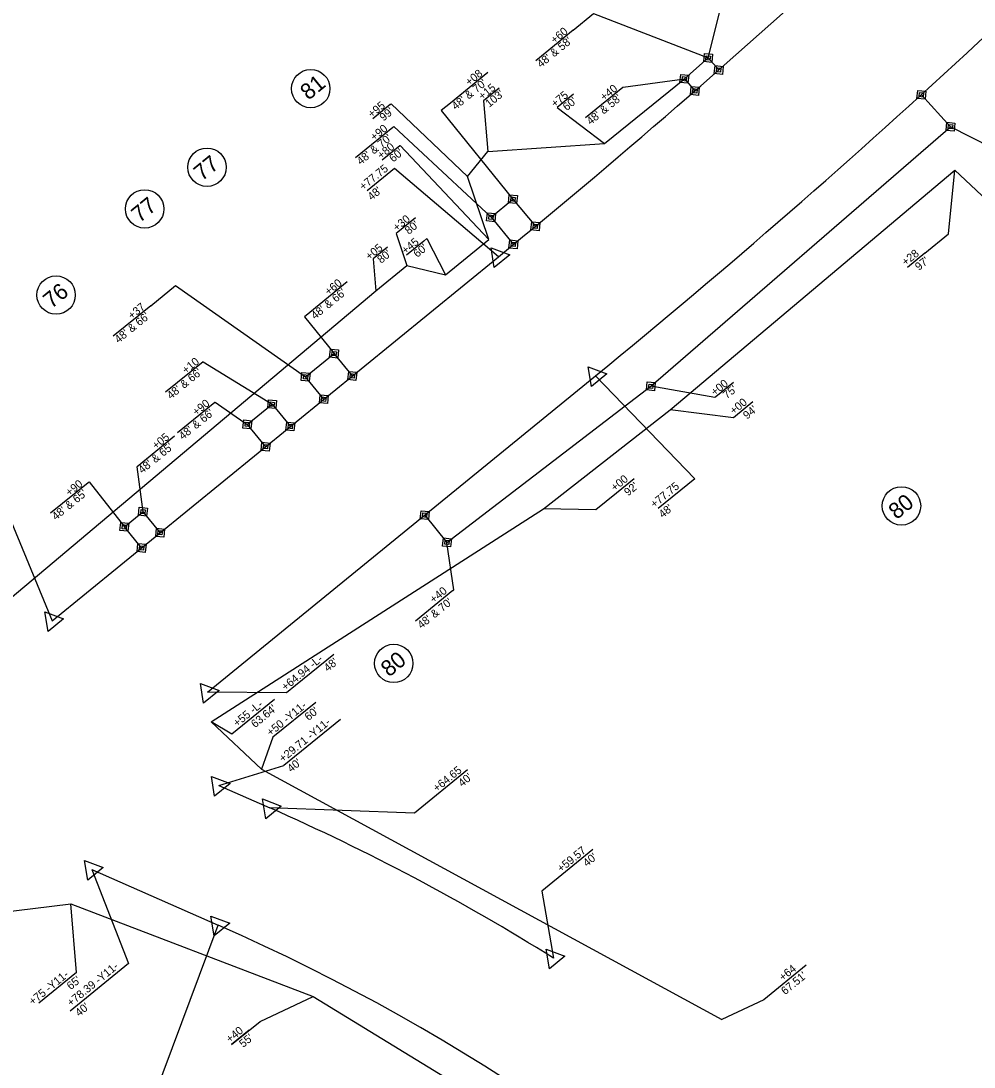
# Model space of a CAD drawing. Extents: x 2320946 to 2332748, y 597838 to 612698.
# Drawn here: x 2326517 to 2327112, y 601762 to 602416 of the extents above; entities that cross this region are included whole.
import ezdxf

# ---------------------------------------------------------------- set-up
doc = ezdxf.new("R2010")
doc.units = 0
for name, color, linetype in [('Prop Easement Construction', 7, 'Continuous'), ('Prop Easement Construction Station Offsets', 7, 'Continuous'), ('Prop Easement Permanent Drainage', 7, 'Continuous'), ('Prop Easement Permanent Drainage Station Offsets', 7, 'Continuous'), ('Prop Parcel Number CELL', 7, 'Continuous'), ('Prop ROW Marker CELL', 7, 'Continuous'), ('Prop ROW Permanent Easement CELL', 7, 'Continuous'), ('Prop ROW RW Lines', 7, 'Continuous'), ('Prop ROW Station Offsets', 7, 'Continuous')]:
    doc.layers.add(name, color=color, linetype=linetype)

msp = doc.modelspace()

# ---------------------------------------------------------------- linework, layer by layer
at = {"layer": 'Prop Easement Construction'}
for p, q in [((2326946.26, 602392.43), (2326953.47, 602421.5)), ((2326881.42, 602339.01), (2326931.39, 602379.41)), ((2326808.58, 602334.01), (2326881.42, 602339.01)), ((2326796.02, 602318.45), (2326808.58, 602334.01)), ((2326809.33, 602278.94), (2326796.02, 602318.45)), ((2326922.53, 602172.61), (2327100.38, 602322.22)), ((2327100.38, 602322.22), (2327166.14, 602260.35)), ((2326782.23, 602256.82), (2326809.33, 602278.94)), ((2326738.6, 602247.02), (2326757.97, 602262.83)), ((2326757.97, 602262.83), (2326782.23, 602256.82)), ((2326483.68, 602032.45), (2326738.6, 602247.02)), ((2326843.5, 602110.62), (2326922.53, 602172.61)), ((2326635.78, 601977.65), (2326843.5, 602110.62)), ((2326635.78, 601977.65), (2326667.14, 601948.01)), ((2326667.14, 601948.01), (2326954.86, 601791.51)), ((2326495.23, 601857.27), (2326548.1, 601863.86)), ((2326548.1, 601863.86), (2326699.47, 601805.89))]:
    msp.add_line(p, q, dxfattribs=at)
msp.add_lwpolyline([(2326699.47, 601805.89), (2326871.18, 601700.94), (2326954.31, 601627.16)], dxfattribs=at)
at = {"layer": 'Prop Easement Construction Station Offsets'}
for p, q in [((2326815.75, 602373.66), (2326805.83, 602365.56)), ((2326862.07, 602369.8), (2326851.86, 602361.46)), ((2326747.59, 602363.27), (2326736.75, 602354.41)), ((2326851.86, 602361.46), (2326881.42, 602339.01)), ((2326753.62, 602337.59), (2326742.65, 602328.63)), ((2326763.37, 602292.46), (2326752.4, 602283.5)), ((2326745.88, 602274.17), (2326736.95, 602266.89)), ((2326768.67, 602278.03), (2326757.82, 602269.18)), ((2326736.95, 602266.89), (2326738.6, 602247.02)), ((2327081.66, 602270.42), (2327070.76, 602261.52)), ((2326974.28, 602177.47), (2326963.31, 602168.51)), ((2326899.95, 602129.51), (2326888.98, 602120.56)), ((2326675.34, 601991.56), (2326648.66, 601969.79)), ((2326701.15, 601989.77), (2326674.38, 601967.91)), ((2326674.38, 601967.91), (2326667.14, 601948.01)), ((2327007.54, 601825.55), (2326980.97, 601803.86)), ((2326551.74, 601820.95), (2326528.19, 601801.73)), ((2326659.48, 601784.86), (2326648.51, 601775.91))]:
    msp.add_line(p, q, dxfattribs=at)
for points in [[(2326805.83, 602365.56), (2326808.58, 602334.01)], [(2326747.59, 602363.27), (2326748.27, 602363.82), (2326796.02, 602318.45)], [(2326753.62, 602337.59), (2326753.85, 602337.78), (2326809.33, 602278.94)], [(2327081.66, 602270.42), (2327096.43, 602282.48), (2327100.38, 602322.22)], [(2326752.4, 602283.5), (2326751.36, 602282.66), (2326757.97, 602262.83)], [(2326768.67, 602278.03), (2326770.56, 602279.57), (2326782.23, 602256.82)], [(2326963.31, 602168.51), (2326962.06, 602167.49), (2326922.53, 602172.61)], [(2326888.98, 602120.56), (2326876.03, 602109.98), (2326843.5, 602110.62)], [(2326648.66, 601969.79), (2326635.78, 601977.65)], [(2326551.74, 601820.95), (2326548.1, 601863.86)], [(2326648.51, 601775.91), (2326666.32, 601790.44), (2326699.47, 601805.89)], [(2326980.97, 601803.86), (2326954.86, 601791.51)]]:
    msp.add_lwpolyline(points, dxfattribs=at)
at = {"layer": 'Prop Easement Permanent Drainage'}
for p, q in [((2326931.39, 602379.41), (2326946.26, 602392.43)), ((2326946.26, 602392.43), (2326952.86, 602384.92)), ((2326931.39, 602379.41), (2326937.97, 602371.87)), ((2327097.65, 602349.45), (2327079.47, 602369.41)), ((2326910.44, 602187.28), (2327097.65, 602349.45)), ((2326810.63, 602292.93), (2326824.32, 602304.21)), ((2326824.32, 602304.21), (2326838.34, 602287.25)), ((2326810.63, 602292.93), (2326824.58, 602275.92)), ((2326694.78, 602193.17), (2326712.6, 602207.71)), ((2326723.98, 602193.77), (2326712.6, 602207.71)), ((2326706.16, 602179.22), (2326694.78, 602193.17)), ((2326783.11, 602089.71), (2326910.44, 602187.28)), ((2326658.37, 602163.44), (2326673.86, 602176.09)), ((2326673.86, 602176.09), (2326685.25, 602162.15)), ((2326658.37, 602163.44), (2326669.76, 602149.5)), ((2326581.54, 602099.43), (2326593.16, 602108.91)), ((2326593.16, 602108.91), (2326603.91, 602095.75)), ((2326769.2, 602106.76), (2326783.11, 602089.71)), ((2326592.29, 602086.26), (2326581.54, 602099.43))]:
    msp.add_line(p, q, dxfattribs=at)
at = {"layer": 'Prop Easement Permanent Drainage Station Offsets'}
for p, q in [((2326861.9, 602409.71), (2326838.55, 602390.64)), ((2326808.63, 602383.36), (2326785.28, 602364.29)), ((2326892.9, 602373.99), (2326869.55, 602354.93)), ((2326749.29, 602348.99), (2326725.94, 602329.93)), ((2327123.4, 602336.27), (2327097.65, 602349.45)), ((2326720.76, 602252.47), (2326697.41, 602233.4)), ((2326598.02, 602237.6), (2326574.66, 602218.53)), ((2326630.69, 602202.59), (2326607.34, 602183.53)), ((2326962.05, 602189.69), (2326951.08, 602180.74)), ((2326638.16, 602177.23), (2326614.81, 602158.16)), ((2326612.8, 602156.06), (2326589.45, 602137)), ((2326558.86, 602126.97), (2326535.5, 602107.9)), ((2326786.81, 602059.59), (2326763.46, 602040.52))]:
    msp.add_line(p, q, dxfattribs=at)
for points in [[(2326861.9, 602409.71), (2326874.72, 602420.17), (2326946.26, 602392.43)], [(2326892.9, 602373.99), (2326893.22, 602374.25), (2326931.39, 602379.41)], [(2326785.28, 602364.29), (2326779.51, 602359.59), (2326824.32, 602304.21)], [(2326749.29, 602348.99), (2326749.96, 602349.54), (2326810.63, 602292.93)], [(2326598.02, 602237.6), (2326613.53, 602250.26), (2326694.78, 602193.17)], [(2326697.41, 602233.4), (2326694.06, 602230.67), (2326712.6, 602207.71)], [(2326630.69, 602202.59), (2326630.73, 602202.62), (2326673.86, 602176.09)], [(2326951.08, 602180.74), (2326950.47, 602180.24), (2326910.44, 602187.28)], [(2326638.16, 602177.23), (2326638.29, 602177.33), (2326658.37, 602163.44)], [(2326589.45, 602137), (2326589.32, 602136.89), (2326593.16, 602108.91)], [(2326558.86, 602126.97), (2326559.65, 602127.62), (2326581.54, 602099.43)], [(2326786.81, 602059.59), (2326787.45, 602060.11), (2326783.11, 602089.71)]]:
    msp.add_lwpolyline(points, dxfattribs=at)
at = {"layer": 'Prop Parcel Number CELL'}
for p, q in [((2326697.99, 602373.29), (2326697.99, 602373.29)), ((2326633.19, 602324.17), (2326633.19, 602324.17)), ((2326594.23, 602298.12), (2326594.23, 602298.12)), ((2326538.92, 602244.29), (2326538.92, 602244.29)), ((2327067.03, 602112.52), (2327067.03, 602112.52)), ((2326749.87, 602014.1), (2326749.87, 602014.1))]:
    msp.add_line(p, q, dxfattribs=at)
for centre in [(2326697.99, 602373.29), (2326633.19, 602324.17), (2326594.23, 602298.12), (2326538.92, 602244.29), (2327067.03, 602112.52), (2326749.87, 602014.1)]:
    msp.add_circle(centre, 12, dxfattribs=at)
at = {"layer": 'Prop ROW Marker CELL'}
for p, q in [((2326946.26, 602392.43), (2326946.26, 602392.43)), ((2326952.86, 602384.92), (2326952.86, 602384.92)), ((2326931.39, 602379.41), (2326931.39, 602379.41)), ((2326937.97, 602371.87), (2326937.97, 602371.87)), ((2327079.47, 602369.41), (2327079.47, 602369.41)), ((2327097.65, 602349.45), (2327097.65, 602349.45)), ((2326824.32, 602304.21), (2326824.32, 602304.21)), ((2326810.63, 602292.93), (2326810.63, 602292.93)), ((2326838.34, 602287.25), (2326838.34, 602287.25)), ((2326824.58, 602275.92), (2326824.58, 602275.92)), ((2326815.2, 602268.24), (2326815.2, 602268.24)), ((2326712.6, 602207.71), (2326712.6, 602207.71)), ((2326694.78, 602193.17), (2326694.78, 602193.17)), ((2326723.98, 602193.77), (2326723.98, 602193.77)), ((2326875.91, 602193.87), (2326875.91, 602193.87)), ((2326910.44, 602187.28), (2326910.44, 602187.28)), ((2326673.86, 602176.09), (2326673.86, 602176.09)), ((2326706.16, 602179.22), (2326706.16, 602179.22)), ((2326658.37, 602163.44), (2326658.37, 602163.44)), ((2326685.25, 602162.15), (2326685.25, 602162.15)), ((2326669.76, 602149.5), (2326669.76, 602149.5)), ((2326593.16, 602108.91), (2326593.16, 602108.91)), ((2326769.2, 602106.76), (2326769.2, 602106.76)), ((2326581.54, 602099.43), (2326581.54, 602099.43)), ((2326603.91, 602095.75), (2326603.91, 602095.75)), ((2326783.11, 602089.71), (2326783.11, 602089.71)), ((2326592.29, 602086.26), (2326592.29, 602086.26)), ((2326536.48, 602040.69), (2326536.48, 602040.69)), ((2326633.59, 601996.05), (2326633.59, 601996.05)), ((2326640.51, 601937.89), (2326640.51, 601937.89)), ((2326672.48, 601923.8), (2326672.48, 601923.8)), ((2326561.29, 601885.37), (2326561.29, 601885.37)), ((2326640.22, 601850.59), (2326640.22, 601850.59)), ((2326849.67, 601829.92), (2326849.67, 601829.92))]:
    msp.add_line(p, q, dxfattribs=at)
for points in [[(2326812.63, 602261.5), (2326810.64, 602273.81), (2326822.31, 602269.4)], [(2326873.34, 602187.13), (2326871.35, 602199.45), (2326883.02, 602195.04)], [(2326533.91, 602033.95), (2326531.92, 602046.27), (2326543.6, 602041.86)], [(2326631.03, 601989.31), (2326629.04, 602001.62), (2326640.71, 601997.21)], [(2326637.94, 601931.15), (2326635.95, 601943.47), (2326647.63, 601939.05)], [(2326669.92, 601917.06), (2326667.93, 601929.38), (2326679.6, 601924.96)], [(2326558.72, 601878.63), (2326556.74, 601890.95), (2326568.41, 601886.54)], [(2326637.66, 601843.85), (2326635.67, 601856.17), (2326647.34, 601851.76)], [(2326847.11, 601823.18), (2326845.12, 601835.49), (2326856.79, 601831.08)]]:
    msp.add_lwpolyline(points, close=True, dxfattribs=at)
at = {"layer": 'Prop ROW Permanent Easement CELL'}
for points in [[(2326943.98, 602395.22), (2326949.05, 602394.71), (2326948.53, 602389.64), (2326943.47, 602390.15)], [(2326945.12, 602393.83), (2326947.65, 602393.57), (2326947.39, 602391.04), (2326944.86, 602391.29)], [(2326950.59, 602387.71), (2326955.65, 602387.2), (2326955.14, 602382.14), (2326950.07, 602382.65)], [(2326951.72, 602386.32), (2326954.26, 602386.06), (2326954, 602383.53), (2326951.47, 602383.79)], [(2326929.11, 602382.19), (2326934.18, 602381.68), (2326933.67, 602376.62), (2326928.6, 602377.13)], [(2326930.25, 602380.8), (2326932.78, 602380.54), (2326932.53, 602378.01), (2326930, 602378.27)], [(2326935.69, 602374.66), (2326940.75, 602374.15), (2326940.24, 602369.08), (2326935.18, 602369.59)], [(2326936.83, 602373.27), (2326939.36, 602373.01), (2326939.1, 602370.48), (2326936.57, 602370.73)], [(2327077.2, 602372.2), (2327082.26, 602371.69), (2327081.75, 602366.62), (2327076.69, 602367.14)], [(2327078.34, 602370.81), (2327080.87, 602370.55), (2327080.61, 602368.02), (2327078.08, 602368.27)], [(2327095.37, 602352.24), (2327100.44, 602351.72), (2327099.93, 602346.66), (2327094.86, 602347.17)], [(2327096.51, 602350.84), (2327099.04, 602350.59), (2327098.79, 602348.05), (2327096.26, 602348.31)], [(2326822.05, 602307), (2326827.11, 602306.48), (2326826.6, 602301.42), (2326821.53, 602301.93)], [(2326823.18, 602305.6), (2326825.72, 602305.34), (2326825.46, 602302.81), (2326822.93, 602303.07)], [(2326808.35, 602295.71), (2326813.41, 602295.2), (2326812.9, 602290.14), (2326807.84, 602290.65)], [(2326809.49, 602294.32), (2326812.02, 602294.06), (2326811.76, 602291.53), (2326809.23, 602291.79)], [(2326836.06, 602290.04), (2326841.13, 602289.53), (2326840.62, 602284.46), (2326835.55, 602284.97)], [(2326837.2, 602288.64), (2326839.73, 602288.39), (2326839.48, 602285.86), (2326836.95, 602286.11)], [(2326822.3, 602278.71), (2326827.37, 602278.19), (2326826.86, 602273.13), (2326821.79, 602273.64)], [(2326823.44, 602277.31), (2326825.97, 602277.06), (2326825.72, 602274.52), (2326823.19, 602274.78)], [(2326710.32, 602210.5), (2326715.39, 602209.99), (2326714.87, 602204.92), (2326709.81, 602205.44)], [(2326711.46, 602209.11), (2326713.99, 602208.85), (2326713.73, 602206.32), (2326711.2, 602206.57)], [(2326692.5, 602195.96), (2326697.57, 602195.44), (2326697.06, 602190.38), (2326691.99, 602190.89)], [(2326693.64, 602194.56), (2326696.17, 602194.31), (2326695.92, 602191.77), (2326693.39, 602192.03)], [(2326721.7, 602196.56), (2326726.77, 602196.05), (2326726.26, 602190.98), (2326721.19, 602191.49)], [(2326722.84, 602195.16), (2326725.37, 602194.91), (2326725.12, 602192.37), (2326722.59, 602192.63)], [(2326908.17, 602190.07), (2326913.23, 602189.56), (2326912.72, 602184.49), (2326907.66, 602185)], [(2326909.31, 602188.67), (2326911.84, 602188.42), (2326911.58, 602185.88), (2326909.05, 602186.14)], [(2326703.89, 602182.01), (2326708.95, 602181.5), (2326708.44, 602176.44), (2326703.37, 602176.95)], [(2326671.59, 602178.88), (2326676.65, 602178.37), (2326676.14, 602173.3), (2326671.08, 602173.81)], [(2326672.73, 602177.49), (2326675.26, 602177.23), (2326675, 602174.7), (2326672.47, 602174.95)], [(2326705.02, 602180.62), (2326707.56, 602180.36), (2326707.3, 602177.83), (2326704.77, 602178.08)], [(2326656.1, 602166.23), (2326661.16, 602165.72), (2326660.65, 602160.66), (2326655.58, 602161.17)], [(2326657.23, 602164.84), (2326659.77, 602164.58), (2326659.51, 602162.05), (2326656.98, 602162.31)], [(2326682.97, 602164.94), (2326688.04, 602164.42), (2326687.52, 602159.36), (2326682.46, 602159.87)], [(2326684.11, 602163.54), (2326686.64, 602163.29), (2326686.39, 602160.75), (2326683.85, 602161.01)], [(2326667.48, 602152.29), (2326672.54, 602151.78), (2326672.03, 602146.71), (2326666.97, 602147.22)], [(2326668.62, 602150.89), (2326671.15, 602150.64), (2326670.89, 602148.11), (2326668.36, 602148.36)], [(2326590.88, 602111.7), (2326595.95, 602111.19), (2326595.44, 602106.13), (2326590.37, 602106.64)], [(2326592.02, 602110.31), (2326594.55, 602110.05), (2326594.3, 602107.52), (2326591.77, 602107.78)], [(2326766.92, 602109.54), (2326771.99, 602109.03), (2326771.47, 602103.97), (2326766.41, 602104.48)], [(2326768.06, 602108.15), (2326770.59, 602107.89), (2326770.34, 602105.36), (2326767.8, 602105.62)], [(2326579.26, 602102.22), (2326584.33, 602101.7), (2326583.82, 602096.64), (2326578.75, 602097.15)], [(2326580.4, 602100.82), (2326582.94, 602100.57), (2326582.68, 602098.03), (2326580.15, 602098.29)], [(2326601.63, 602098.53), (2326606.7, 602098.02), (2326606.19, 602092.96), (2326601.12, 602093.47)], [(2326602.77, 602097.14), (2326605.31, 602096.88), (2326605.05, 602094.35), (2326602.52, 602094.61)], [(2326780.83, 602092.5), (2326785.9, 602091.99), (2326785.39, 602086.93), (2326780.32, 602087.44)], [(2326781.97, 602091.11), (2326784.51, 602090.85), (2326784.25, 602088.32), (2326781.72, 602088.58)], [(2326590.02, 602089.05), (2326595.08, 602088.54), (2326594.57, 602083.47), (2326589.5, 602083.98)], [(2326591.15, 602087.65), (2326593.69, 602087.4), (2326593.43, 602084.87), (2326590.9, 602085.12)]]:
    msp.add_lwpolyline(points, close=True, dxfattribs=at)
at = {"layer": 'Prop ROW RW Lines'}
for p, q in [((2326536.48, 602040.69), (2326815.2, 602268.24)), ((2326633.59, 601996.05), (2326875.91, 602193.87)), ((2326640.51, 601937.89), (2326672.48, 601923.8)), ((2326561.29, 601885.37), (2326640.22, 601850.59))]:
    msp.add_line(p, q, dxfattribs=at)
for centre, radius, start, end in [((2323721.46, 606057.75), 4892, 309.22799, 316.52652), ((2323721.46, 606057.75), 4988, 309.22799, 316.52652), ((2326111.99, 600651.81), 1390, 57.94704, 66.2198), ((2326111.99, 600651.81), 1310, 22.46921, 66.2198)]:
    msp.add_arc(centre, radius, start, end, dxfattribs=at)
at = {"layer": 'Prop ROW Station Offsets'}
for p, q in [((2326750.37, 602323.38), (2326733.21, 602309.37)), ((2326815.2, 602268.24), (2326750.37, 602323.38)), ((2326875.91, 602193.87), (2326937.88, 602129.52)), ((2326937.88, 602129.52), (2326915.07, 602110.9)), ((2326712.34, 602019.73), (2326688.41, 602000.2)), ((2326716.5, 601979.08), (2326681.28, 601950.33)), ((2326640.51, 601937.89), (2326681.28, 601950.33)), ((2326796, 601947.53), (2326762.81, 601920.43)), ((2326874.26, 601897.86), (2326842.31, 601871.77)), ((2326561.29, 601885.37), (2326584.05, 601826.49)), ((2326584.05, 601826.49), (2326547.79, 601796.89))]:
    msp.add_line(p, q, dxfattribs=at)
for points in [[(2326478.62, 602180.4), (2326536.48, 602040.69)], [(2326688.41, 602000.2), (2326682.82, 601995.63), (2326633.59, 601996.05)], [(2326762.81, 601920.43), (2326672.48, 601923.8)], [(2326842.31, 601871.77), (2326849.67, 601829.92)], [(2326599.97, 601742.86), (2326640.22, 601850.59)]]:
    msp.add_lwpolyline(points, dxfattribs=at)

# ---------------------------------------------------------------- texts
at = {"layer": 'Prop Easement Construction Station Offsets'}
for s, p in [('+15', (2326805.24, 602365.88)), ("103'", (2326809.51, 602361.3)), ('+75', (2326850.58, 602361.23)), ('+95', (2326736.16, 602354.74)), ("60'", (2326857.92, 602359.15)), ("99'", (2326743.49, 602352.66)), ('+80', (2326742.03, 602328.93)), ("60'", (2326749.52, 602326.98)), ('+30', (2326751.78, 602283.8)), ("80'", (2326759.27, 602281.85)), ('+45', (2326757.23, 602269.5)), ('+05', (2326734.66, 602265.82)), ("80'", (2326742, 602263.75)), ("60'", (2326764.57, 602267.43)), ('+28', (2327069.68, 602262.26)), ("97'", (2327077.96, 602259.33)), ('+00', (2326962.29, 602169.3)), ("94'", (2326970.57, 602166.38)), ('+00', (2326887.96, 602121.34)), ("92'", (2326896.25, 602118.42)), ('+55 -L-', (2326652.03, 601974.15)), ("63.64'", (2326663.17, 601973.56)), ('+50 -Y11-', (2326672.94, 601968.35)), ("60'", (2326696.64, 601978.01)), ('+64 ', (2326993, 601815.3)), ("67.51'", (2326994.34, 601806.71)), ('+75 -Y11-', (2326524.34, 601800.2)), ("65'", (2326548.04, 601809.86)), ('+40', (2326647.5, 601776.69)), ("55'", (2326655.78, 601773.77))]:
    msp.add_text(s, height=5, rotation=39.22799, dxfattribs=at).set_placement(p)
at = {"layer": 'Prop Easement Permanent Drainage Station Offsets'}
for s, p in [('+60', (2326850.31, 602401.05)), ("48' & 58'", (2326841.8, 602386.04)), ('+08', (2326797.05, 602374.71)), ("48' & 70'", (2326788.53, 602359.69)), ('+40', (2326881.31, 602365.33)), ("48' & 58'", (2326872.8, 602350.32)), ("48' & 70'", (2326729.2, 602325.32)), ('+90', (2326737.7, 602340.34)), ('+60', (2326709.17, 602243.81)), ("48' & 66'", (2326700.66, 602228.8)), ("48' & 66'", (2326577.92, 602213.93)), ('+37', (2326586.25, 602228.8)), ('+10', (2326620.03, 602194.69)), ("48' & 66'", (2326610.6, 602178.92)), ('+00', (2326950.45, 602181.03)), ("75'", (2326957.95, 602179.08)), ('+90', (2326626.57, 602168.57)), ("48' & 66'", (2326618.07, 602153.56)), ('+05', (2326601.36, 602147.53)), ("48' & 65'", (2326592.7, 602132.39)), ("48' & 65'", (2326538.76, 602103.3)), ('+90', (2326547.26, 602118.31)), ('+40', (2326774.82, 602051.42)), ("48' & 70'", (2326767.11, 602035.44))]:
    msp.add_text(s, height=5, rotation=39.22799, dxfattribs=at).set_placement(p)
at = {"layer": 'Prop Parcel Number CELL'}
for s, p in [('81', (2326696.56, 602365.67)), ('77', (2326630.05, 602315.16)), ('77', (2326591.09, 602289.1)), ('76', (2326535.98, 602235.44)), ('80', (2327064.07, 602103.65)), ('80', (2326746.91, 602005.23))]:
    msp.add_text(s, height=10, rotation=39.22799, dxfattribs=at).set_placement(p)
at = {"layer": 'Prop ROW Station Offsets'}
for s, p in [('+77.75', (2326730.84, 602309.44)), ("48'", (2326735.98, 602303.14)), ('+77.75', (2326912.71, 602110.96)), ("48'", (2326917.85, 602104.67)), ("48'", (2326708.64, 602008.64)), ('+64.94 -L-', (2326682.18, 601996.72)), ('+29.71 -Y11-', (2326680.68, 601952.04)), ("40'", (2326685.81, 601945.74)), ('+64.65 ', (2326776.81, 601933.48)), ("40'", (2326792.6, 601936.68)), ('+59.57 ', (2326854.44, 601883.29)), ("40'", (2326870.56, 601886.76)), ('+78.39 -Y11-', (2326548.2, 601799.43)), ("40'", (2326553.34, 601793.14))]:
    msp.add_text(s, height=5, rotation=39.22799, dxfattribs=at).set_placement(p)

doc.saveas('drawing.dxf')
